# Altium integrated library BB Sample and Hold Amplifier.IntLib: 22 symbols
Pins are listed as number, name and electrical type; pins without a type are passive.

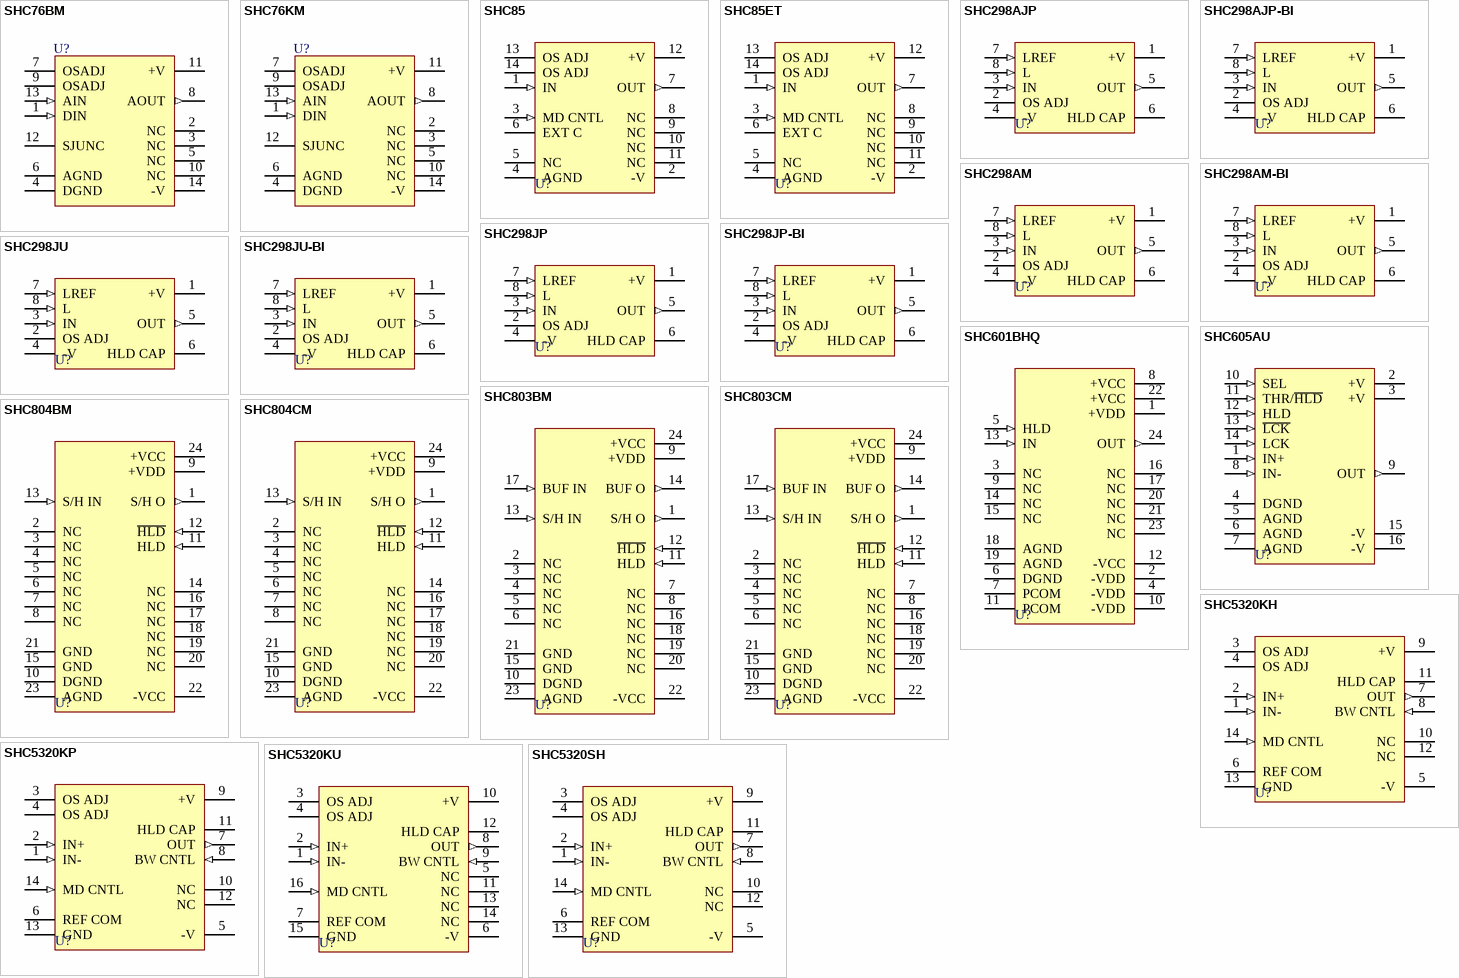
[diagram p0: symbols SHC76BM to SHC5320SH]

## SHC76BM
designator U?
Sample/Hold Amplifier; Note: Pins 2,3,5 and 10 are No internal Connection (NC) pins.
footprint ZZ107 (DIP; 14 Round Pins; Row Space 7.62 mm; Pitch 2.54 mm)
pins: 1 DIN (in), 2 NC, 3 NC, 4 DGND (power), 5 NC, 6 AGND (power), 7 OSADJ, 8 AOUT (out), 9 OSADJ, 10 NC, 11 +V, 12 SJUNC, 13 AIN (in), 14 -V (power)

## SHC76KM
designator U?
Sample/Hold Amplifier; Note: Pins 2,3,5 and 10 are No internal Connection (NC) pins.
footprint ZZ107 (DIP; 14 Round Pins; Row Space 7.62 mm; Pitch 2.54 mm)
pins: 1 DIN (in), 2 NC, 3 NC, 4 DGND (power), 5 NC, 6 AGND (power), 7 OSADJ, 8 AOUT (out), 9 OSADJ, 10 NC, 11 +V, 12 SJUNC, 13 AIN (in), 14 -V (power)

## SHC85
designator U?
Fast IC Sample/Hold Amplifier; Note: Pins 5 and 8-11 are No internal Connection (NC) pins.
footprint ZZ107 (DIP; 14 Round Pins; Row Space 7.62 mm; Pitch 2.54 mm)
pins: 1 IN (in), 2 -V (power), 3 MD CNTL (in), 4 AGND (power), 5 NC, 6 EXT C, 7 OUT (out), 8 NC, 9 NC, 10 NC, 11 NC, 12 +V (power), 13 OS ADJ, 14 OS ADJ

## SHC85ET
designator U?
Fast IC Sample/Hold Amplifier; Note: Pins 5 and 8-11 are No internal Connection (NC) pins.
footprint ZZ107 (DIP; 14 Round Pins; Row Space 7.62 mm; Pitch 2.54 mm)
pins: 1 IN (in), 2 -V (power), 3 MD CNTL (in), 4 AGND (power), 5 NC, 6 EXT C, 7 OUT (out), 8 NC, 9 NC, 10 NC, 11 NC, 12 +V (power), 13 OS ADJ, 14 OS ADJ

## SHC298AJP
designator U?
Monolithic Sample/Hold Amplifier
footprint 006E (DIP; 8 Leads; Row Spacing 7.62 mm; Pitch 2.54 mm)
3D model DIP8 (DIP; 8 Leads; Row Spacing 7.62 mm; Pitch 2.54 mm)
pins: 1 +V (power), 2 OS ADJ, 3 IN (in), 4 -V (power), 5 OUT (out), 6 HLD CAP, 7 LREF (in), 8 L (in)

## SHC298AJP-BI
designator U?
Monolithic Sample/Hold Amplifier; ComponentAvailability: Obsolete
footprint 006E (DIP; 8 Leads; Row Spacing 7.62 mm; Pitch 2.54 mm)
3D model DIP8 (DIP; 8 Leads; Row Spacing 7.62 mm; Pitch 2.54 mm)
pins: 1 +V (power), 2 OS ADJ, 3 IN (in), 4 -V (power), 5 OUT (out), 6 HLD CAP, 7 LREF (in), 8 L (in)

## SHC298AM
designator U?
Monolithic Sample/Hold Amplifier
footprint 001B (Can; 8 Leads; Pin Circle Dia. 5.08 mm (TO-99); Lead Dia. 0.53 mm (max))
pins: 1 +V (power), 2 OS ADJ, 3 IN (in), 4 -V (power), 5 OUT (out), 6 HLD CAP, 7 LREF (in), 8 L (in)

## SHC298AM-BI
designator U?
Monolithic Sample/Hold Amplifier; ComponentAvailability: Obsolete
footprint 001B (Can; 8 Leads; Pin Circle Dia. 5.08 mm (TO-99); Lead Dia. 0.53 mm (max))
pins: 1 +V (power), 2 OS ADJ, 3 IN (in), 4 -V (power), 5 OUT (out), 6 HLD CAP, 7 LREF (in), 8 L (in)

## SHC298JP
designator U?
Monolithic Sample/Hold Amplifier
footprint 006E (DIP; 8 Leads; Row Spacing 7.62 mm; Pitch 2.54 mm)
3D model DIP8 (DIP; 8 Leads; Row Spacing 7.62 mm; Pitch 2.54 mm)
pins: 1 +V (power), 2 OS ADJ, 3 IN (in), 4 -V (power), 5 OUT (out), 6 HLD CAP, 7 LREF (in), 8 L (in)

## SHC298JP-BI
designator U?
Monolithic Sample/Hold Amplifier; ComponentAvailability: Obsolete
footprint 006E (DIP; 8 Leads; Row Spacing 7.62 mm; Pitch 2.54 mm)
3D model DIP8 (DIP; 8 Leads; Row Spacing 7.62 mm; Pitch 2.54 mm)
pins: 1 +V (power), 2 OS ADJ, 3 IN (in), 4 -V (power), 5 OUT (out), 6 HLD CAP, 7 LREF (in), 8 L (in)

## SHC298JU
designator U?
Monolithic Sample/Hold Amplifier
footprint 182H_N (SOIC, 8-Leads, Body 4.9x3.9mm, Pitch 1.27mm, IPC Medium Density)
footprint 182H_L (SOIC, 8-Leads, Body 4.9x3.9mm, Pitch 1.27mm, IPC High Density)
footprint 182H_M (SOIC, 8-Leads, Body 4.9x3.9mm, Pitch 1.27mm, IPC Low Density)
3D model SOIC8 (8-Pin Small Outline Integrated Circuit 1.27 mm Pitch)
pins: 1 +V (power), 2 OS ADJ, 3 IN (in), 4 -V (power), 5 OUT (out), 6 HLD CAP, 7 LREF (in), 8 L (in)

## SHC298JU-BI
designator U?
Monolithic Sample/Hold Amplifier; ComponentAvailability: Obsolete
footprint 182H_N (SOIC, 8-Leads, Body 4.9x3.9mm, Pitch 1.27mm, IPC Medium Density)
footprint 182H_L (SOIC, 8-Leads, Body 4.9x3.9mm, Pitch 1.27mm, IPC High Density)
footprint 182H_M (SOIC, 8-Leads, Body 4.9x3.9mm, Pitch 1.27mm, IPC Low Density)
3D model SOIC8 (8-Pin Small Outline Integrated Circuit 1.27 mm Pitch)
pins: 1 +V (power), 2 OS ADJ, 3 IN (in), 4 -V (power), 5 OUT (out), 6 HLD CAP, 7 LREF (in), 8 L (in)

## SHC601BHQ
designator U?
Ultra-High-Speed Sample/Hold Amplifier; Note: Pins 3,9,14,15,16,17,20,21 and 23 are Not Connected
footprint H24 (DIP; 24 Rectangular Pins; Row Space 15.24 mm; Pitch 2.54 mm)
pins: 1 +VDD (power), 2 -VDD (power), 3 NC, 4 -VDD (power), 5 HLD (in), 6 DGND (power), 7 PCOM (power), 8 +VCC (power), 9 NC, 10 -VDD (power), 11 PCOM (power), 12 -VCC (power), 13 IN (in), 14 NC, 15 NC, 16 NC, 17 NC, 18 AGND (power), 19 AGND (power), 20 NC, 21 NC, 22 +VCC (power), 23 NC, 24 OUT (out)

## SHC605AU
designator U?
High-Speed Operational Track-and-Hold Amplifier
footprint ZZ265_N (SOIC, 16-Leads, Body 9.9x3.9mm, Pitch 1.27mm, IPC Medium Density)
footprint ZZ265_L (SOIC, 16-Leads, Body 9.9x3.9mm, Pitch 1.27mm, IPC High Density)
footprint ZZ265_M (SOIC, 16-Leads, Body 9.9x3.9mm, Pitch 1.27mm, IPC Low Density)
3D model ZZ265 (16-Pin Small Outline Integrated Circuit 1.27 mm Pitch)
pins: 1 IN+ (in), 2 +V (power), 3 +V (power), 4 DGND (power), 5 AGND (power), 6 AGND (power), 7 AGND (power), 8 IN- (in), 9 OUT (out), 10 SEL (in), 11 THR/~{HLD} (in), 12 HLD (in), 13 ~{LCK} (in), 14 LCK (in), 15 -V (power), 16 -V (power)

## SHC803BM
designator U?
Ultra-High-Speed Sample/Hold Amplifier; Note: Pins 2-8,16,18,19 and 20 are No internal Connection (NC) pins. Pin 23 connected to case.
footprint ZZ113 (DIP; 24 Round Pins; Row Space 15.24 mm; Pitch 2.54 mm)
pins: 1 S/H O (out), 2 NC, 3 NC, 4 NC, 5 NC, 6 NC, 7 NC, 8 NC, 9 +VDD (power), 10 DGND (power), 11 HLD (in), 12 ~{HLD} (in), 13 S/H IN (in), 14 BUF O (out), 15 GND (power), 16 NC, 17 BUF IN (in), 18 NC, 19 NC, 20 NC, 21 GND (power), 22 -VCC (power), 23 AGND (power), 24 +VCC (power)

## SHC803CM
designator U?
Ultra-High-Speed Sample/Hold Amplifier; Note: Pins 2-8,16,18,19 and 20 are No internal Connection (NC) pins. Pin 23 connected to case.
footprint ZZ113 (DIP; 24 Round Pins; Row Space 15.24 mm; Pitch 2.54 mm)
pins: 1 S/H O (out), 2 NC, 3 NC, 4 NC, 5 NC, 6 NC, 7 NC, 8 NC, 9 +VDD (power), 10 DGND (power), 11 HLD (in), 12 ~{HLD} (in), 13 S/H IN (in), 14 BUF O (out), 15 GND (power), 16 NC, 17 BUF IN (in), 18 NC, 19 NC, 20 NC, 21 GND (power), 22 -VCC (power), 23 AGND (power), 24 +VCC (power)

## SHC804BM
designator U?
Ultra-High-Speed Sample/Hold Amplifier; Note: Pins 2-8, 14 and 16-20 are No internal Connection (NC) pins. Pin 23 connected to case.
footprint ZZ113 (DIP; 24 Round Pins; Row Space 15.24 mm; Pitch 2.54 mm)
pins: 1 S/H O (out), 2 NC, 3 NC, 4 NC, 5 NC, 6 NC, 7 NC, 8 NC, 9 +VDD (power), 10 DGND (power), 11 HLD (in), 12 ~{HLD} (in), 13 S/H IN (in), 14 NC, 15 GND (power), 16 NC, 17 NC, 18 NC, 19 NC, 20 NC, 21 GND (power), 22 -VCC (power), 23 AGND (power), 24 +VCC (power)

## SHC804CM
designator U?
Ultra-High-Speed Sample/Hold Amplifier; Note: Pins 2-8, 14 and 16-20 are No internal Connection (NC) pins. Pin 23 connected to case.
footprint ZZ113 (DIP; 24 Round Pins; Row Space 15.24 mm; Pitch 2.54 mm)
pins: 1 S/H O (out), 2 NC, 3 NC, 4 NC, 5 NC, 6 NC, 7 NC, 8 NC, 9 +VDD (power), 10 DGND (power), 11 HLD (in), 12 ~{HLD} (in), 13 S/H IN (in), 14 NC, 15 GND (power), 16 NC, 17 NC, 18 NC, 19 NC, 20 NC, 21 GND (power), 22 -VCC (power), 23 AGND (power), 24 +VCC (power)

## SHC5320KH
designator U?
High-Speed Bipolar Monolithic Sample/Hold Amplifier; Note: Pins 10 and 12 are No internal Connection (NC) pins.
footprint 163C (DIP; 14 Leads; Row Spacing 7.62 mm; Pitch 2.54 mm)
3D model 010G (DIP; 14 Leads; Row Spacing 7.62 mm; Pitch 2.54 mm)
pins: 1 IN- (in), 2 IN+ (in), 3 OS ADJ, 4 OS ADJ, 5 -V (power), 6 REF COM (power), 7 OUT (out), 8 BW CNTL (in), 9 +V (power), 10 NC, 11 HLD CAP, 12 NC, 13 GND (power), 14 MD CNTL (in)

## SHC5320KP
designator U?
High-Speed Bipolar Monolithic Sample/Hold Amplifier; Note: Pins 10 and 12 are No internal Connection (NC) pins.
footprint 010G (DIP; 14 Leads; Row Spacing 7.62 mm; Pitch 2.54 mm)
3D model 010G (DIP; 14 Leads; Row Spacing 7.62 mm; Pitch 2.54 mm)
pins: 1 IN- (in), 2 IN+ (in), 3 OS ADJ, 4 OS ADJ, 5 -V (power), 6 REF COM (power), 7 OUT (out), 8 BW CNTL (in), 9 +V (power), 10 NC, 11 HLD CAP, 12 NC, 13 GND (power), 14 MD CNTL (in)

## SHC5320KU
designator U?
High-Speed Bipolar Monolithic Sample/Hold Amplifier; Note: Pins 5,11,13 and 14 are No internal Connection (NC) pins.
footprint 211F_N (SOIC, 16-Leads, Body 10.3x7.5mm, Pitch 1.27mm, IPC Medium Density)
footprint 211F_L (SOIC, 16-Leads, Body 10.3x7.5mm, Pitch 1.27mm, IPC High Density)
footprint 211F_M (SOIC, 16-Leads, Body 10.3x7.5mm, Pitch 1.27mm, IPC Low Density)
3D model SOIC16 (16-Pin Small Outline Integrated Circuit 1.27 mm Pitch)
pins: 1 IN- (in), 2 IN+ (in), 3 OS ADJ, 4 OS ADJ, 5 NC, 6 -V (power), 7 REF COM (power), 8 OUT (out), 9 BW CNTL (in), 10 +V (power), 11 NC, 12 HLD CAP, 13 NC, 14 NC, 15 GND (power), 16 MD CNTL (in)

## SHC5320SH
designator U?
High-Speed Bipolar Monolithic Sample/Hold Amplifier; Note: Pins 10 and 12 are No internal Connection (NC) pins.
footprint 163C (DIP; 14 Leads; Row Spacing 7.62 mm; Pitch 2.54 mm)
3D model 010G (DIP; 14 Leads; Row Spacing 7.62 mm; Pitch 2.54 mm)
pins: 1 IN- (in), 2 IN+ (in), 3 OS ADJ, 4 OS ADJ, 5 -V (power), 6 REF COM (power), 7 OUT (out), 8 BW CNTL (in), 9 +V (power), 10 NC, 11 HLD CAP, 12 NC, 13 GND (power), 14 MD CNTL (in)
